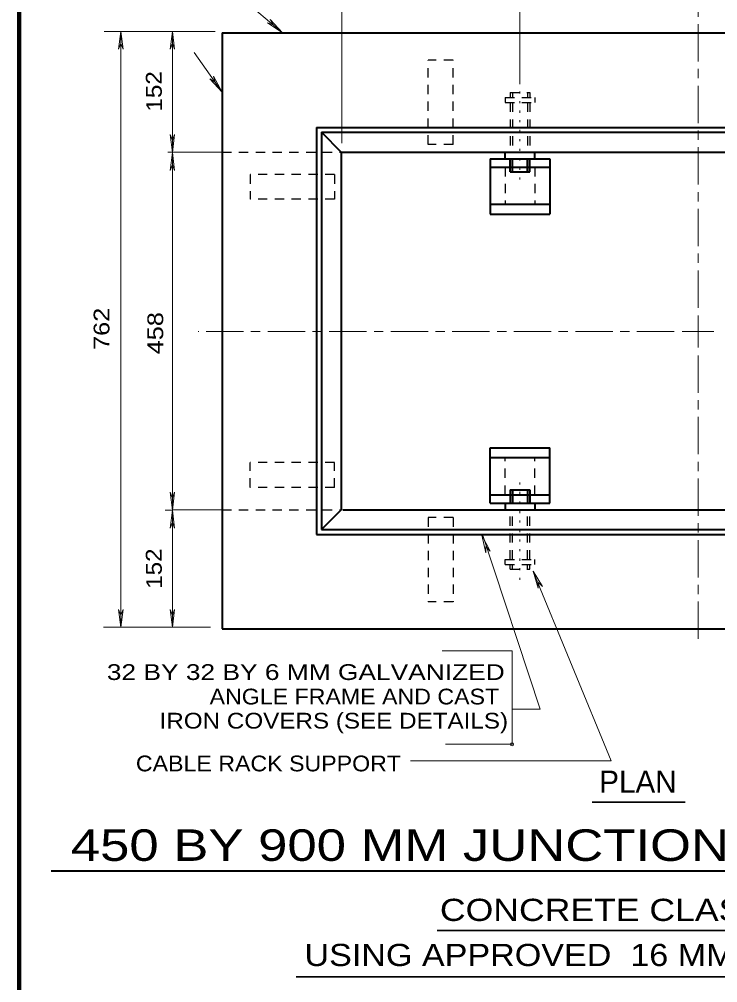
# Model space of a CAD drawing. Extents: x 312583 to 312854, y 144419 to 144597.
# Drawn here: x 312616.5 to 312650.21, y 144526.08 to 144572.55 of the extents above; entities that cross this region are included whole.
import ezdxf
from ezdxf.enums import TextEntityAlignment as Align

# ---------------------------------------------------------------- set-up
doc = ezdxf.new("R2010")
doc.units = 0
doc.header["$LTSCALE"] = 0.3
doc.header["$PDMODE"] = 32
doc.header["$PDSIZE"] = 0.15
for name, pattern in [('DOTTED', [1.5, 0.3, -1.2]), ('LONG_DASH_SHORT_DASH', [9.9, 6, -1.2, 1.5, -1.2]), ('SHORT_DASHED', [2.7, 1.5, -1.2])]:
    doc.linetypes.add(name, pattern=pattern)
doc.layers.add('1', color=7, linetype='Continuous', lineweight=40)
doc.layers.add('2', color=7, linetype='Continuous', lineweight=13)

msp = doc.modelspace()

# ---------------------------------------------------------------- linework, layer by layer
at = {"layer": '1'}
for p, q in [((312626.2931, 144571.8954), (312672.2931, 144571.8954)), ((312626.2931, 144571.8954), (312626.2931, 144543.1454)), ((312630.8471, 144567.3414), (312630.8471, 144547.6994)), ((312631.0848, 144567.1038), (312631.0848, 144547.9371)), ((312631.0848, 144567.1038), (312632.0431, 144566.1454)), ((312632.0431, 144566.1454), (312632.0431, 144548.8954)), ((312632.0508, 144566.1454), (312653.2184, 144566.1454)), ((312639.9551, 144565.8234), (312639.9551, 144566.1454)), ((312641.3888, 144565.8234), (312641.3888, 144566.1454)), ((312639.2344, 144565.8234), (312639.2344, 144563.1478)), ((312639.2344, 144565.8234), (312642.1094, 144565.8234)), ((312640.1928, 144565.1871), (312640.1928, 144565.8234)), ((312640.3078, 144565.1871), (312640.3078, 144565.8234)), ((312641.0284, 144565.1871), (312641.0284, 144565.8234)), ((312641.1511, 144565.1871), (312641.1511, 144565.8234)), ((312642.1094, 144565.8234), (312642.1094, 144563.1478)), ((312639.2344, 144565.4248), (312642.1094, 144565.4248)), ((312640.1928, 144565.1871), (312641.1511, 144565.1871)), ((312639.2344, 144563.6308), (312642.1094, 144563.6308)), ((312639.2344, 144563.1478), (312642.1094, 144563.1478)), ((312639.2344, 144551.8854), (312642.1094, 144551.8854)), ((312639.2344, 144549.2174), (312639.2344, 144551.8854)), ((312642.1094, 144549.2174), (312642.1094, 144551.8854)), ((312639.2344, 144551.4101), (312642.1094, 144551.4101)), ((312640.1928, 144549.8538), (312641.1511, 144549.8538)), ((312640.1928, 144549.8538), (312640.1928, 144549.2174)), ((312640.3078, 144549.8538), (312640.3078, 144549.2174)), ((312641.0284, 144549.8538), (312641.0284, 144549.2174)), ((312641.1511, 144549.8538), (312641.1511, 144549.2174)), ((312639.2344, 144549.6161), (312642.1094, 144549.6161)), ((312632.0431, 144548.8954), (312631.0848, 144547.9371)), ((312632.1121, 144548.8954), (312666.5354, 144548.8954)), ((312639.2344, 144549.2174), (312642.1094, 144549.2174)), ((312639.9551, 144549.2174), (312639.9551, 144548.8954)), ((312641.3888, 144549.2174), (312641.3888, 144548.8954)), ((312631.0848, 144547.9371), (312667.5014, 144547.9371)), ((312630.8471, 144547.6994), (312667.7468, 144547.6994)), ((312626.2931, 144543.1454), (312672.2931, 144543.1454))]:
    msp.add_line(p, q, dxfattribs=at)
at = {"layer": '1', "linetype": 'SHORT_DASHED', "lineweight": 25}
for p, q in [((312637.4404, 144570.5844), (312636.2368, 144570.5844)), ((312636.2368, 144566.5134), (312636.2368, 144570.5844)), ((312637.4404, 144566.5134), (312637.4404, 144570.5844)), ((312640.1928, 144569.0204), (312641.1511, 144569.0204)), ((312640.1928, 144569.0204), (312640.1928, 144568.7828)), ((312640.3078, 144569.0204), (312640.3078, 144568.7828)), ((312641.0284, 144569.0204), (312641.0284, 144568.7828)), ((312641.1511, 144569.0204), (312641.1511, 144568.7828)), ((312639.9551, 144568.7828), (312641.3888, 144568.7828)), ((312639.9551, 144568.7828), (312639.9551, 144568.5374)), ((312639.9551, 144568.5374), (312641.3888, 144568.5374)), ((312640.1928, 144568.5374), (312640.1928, 144566.1454)), ((312640.3078, 144568.5374), (312640.3078, 144566.1454)), ((312641.0284, 144568.5374), (312641.0284, 144566.1454)), ((312641.1511, 144568.5374), (312641.1511, 144566.1454)), ((312641.3888, 144568.7828), (312641.3888, 144568.5374)), ((312637.4404, 144566.5134), (312636.2368, 144566.5134)), ((312626.2931, 144566.1454), (312632.0508, 144566.1454)), ((312639.9551, 144565.4248), (312639.9551, 144563.6308)), ((312641.3888, 144565.4248), (312641.3888, 144563.6308)), ((312627.6424, 144565.0644), (312627.6424, 144563.8684)), ((312631.7134, 144565.0644), (312627.6424, 144565.0644)), ((312631.7134, 144565.0644), (312631.7134, 144563.8684)), ((312631.7134, 144563.8684), (312627.6424, 144563.8684)), ((312627.6424, 144549.9688), (312627.6424, 144551.1724)), ((312631.7134, 144551.1724), (312627.6424, 144551.1724)), ((312631.7134, 144549.9688), (312631.7134, 144551.1724)), ((312639.9551, 144549.6161), (312639.9551, 144551.4101)), ((312641.3888, 144549.6161), (312641.3888, 144551.4101)), ((312631.7134, 144549.9688), (312627.6424, 144549.9688)), ((312626.2931, 144548.8954), (312632.0431, 144548.8954)), ((312640.1928, 144546.4958), (312640.1928, 144548.8954)), ((312640.3078, 144546.4958), (312640.3078, 144548.8954)), ((312641.0284, 144546.4958), (312641.0284, 144548.8954)), ((312641.1511, 144546.4958), (312641.1511, 144548.8954)), ((312637.4404, 144548.5274), (312636.2368, 144548.5274)), ((312636.2368, 144548.5274), (312636.2368, 144544.4564)), ((312637.4404, 144548.5274), (312637.4404, 144544.4564)), ((312639.9551, 144546.4958), (312641.3888, 144546.4958)), ((312639.9551, 144546.2581), (312639.9551, 144546.4958)), ((312639.9551, 144546.2581), (312641.3888, 144546.2581)), ((312640.1928, 144546.0204), (312640.1928, 144546.2581)), ((312640.3078, 144546.0204), (312640.3078, 144546.2581)), ((312641.0284, 144546.0204), (312641.0284, 144546.2581)), ((312641.1511, 144546.0204), (312641.1511, 144546.2581)), ((312641.3888, 144546.2581), (312641.3888, 144546.4958)), ((312640.1928, 144546.0204), (312641.1511, 144546.0204)), ((312637.4404, 144544.4564), (312636.2368, 144544.4564))]:
    msp.add_line(p, q, dxfattribs=at)
at = {"layer": '1', "linetype": 'DOTTED', "lineweight": 13}
for p, q in [((312640.6681, 144569.5264), (312640.6681, 144564.7041)), ((312640.6681, 144545.5144), (312640.6681, 144550.2524))]:
    msp.add_line(p, q, dxfattribs=at)
at = {"layer": '1', "lineweight": 158}
msp.add_lwpolyline([(312616.5, 144423.1446), (312616.5, 144585.0846), (312849, 144585.0846)], dxfattribs=at)
at = {"layer": '1'}
for points in [[(312630.8471, 144567.3414), (312667.7468, 144567.3414), (312667.7468, 144547.6994)], [(312631.0848, 144567.1038), (312667.5014, 144567.1038), (312667.5014, 144547.9371)]]:
    msp.add_lwpolyline(points, dxfattribs=at)
at = {"layer": '2'}
for p, q in [((312632.0738, 144566.5824), (312632.0738, 144577.3004)), ((312640.6681, 144569.5264), (312640.6681, 144574.7551)), ((312626.8451, 144573.9118), (312629.2064, 144571.8954)), ((312628.6161, 144572.5394), (312628.7618, 144572.2788)), ((312629.2064, 144571.8954), (312628.6161, 144572.5394)), ((312628.4781, 144572.3784), (312628.7618, 144572.2788)), ((312629.2064, 144571.8954), (312628.4781, 144572.3784)), ((312620.6044, 144571.9721), (312625.9634, 144571.9721)), ((312621.4018, 144571.9721), (312621.2944, 144571.1058)), ((312621.4018, 144543.2221), (312621.4018, 144571.9721)), ((312621.4018, 144571.9721), (312621.5091, 144571.1058)), ((312623.8934, 144571.9721), (312623.7861, 144571.1058)), ((312623.8934, 144566.1301), (312623.8934, 144571.9721)), ((312623.8934, 144571.9721), (312624.0008, 144571.1058)), ((312621.2944, 144571.1058), (312621.4018, 144571.3818)), ((312621.5091, 144571.1058), (312621.4018, 144571.3818)), ((312623.7861, 144571.1058), (312623.8934, 144571.3818)), ((312624.0008, 144571.1058), (312623.8934, 144571.3818)), ((312624.9361, 144570.9524), (312626.2931, 144569.0434)), ((312625.8791, 144569.8101), (312625.9558, 144569.5188)), ((312626.2931, 144569.0434), (312625.8791, 144569.8101)), ((312625.7028, 144569.6874), (312625.9558, 144569.5188)), ((312626.2931, 144569.0434), (312625.7028, 144569.6874)), ((312623.7861, 144566.9964), (312623.8934, 144566.7204)), ((312623.8934, 144566.1301), (312623.7861, 144566.9964)), ((312624.0008, 144566.9964), (312623.8934, 144566.7204)), ((312623.8934, 144566.1301), (312624.0008, 144566.9964)), ((312626.2931, 144566.1454), (312623.6711, 144566.1454)), ((312623.8934, 144566.1301), (312623.7861, 144565.2638)), ((312623.8934, 144566.1301), (312624.0008, 144565.2638)), ((312623.7861, 144565.2638), (312623.8934, 144565.5398)), ((312624.0008, 144565.2638), (312623.8934, 144565.5398)), ((312649.2624, 144557.4898), (312649.2624, 144558.2564)), ((312649.2624, 144557.4898), (312648.4958, 144557.4898)), ((312649.2624, 144557.4898), (312649.2624, 144556.7231)), ((312649.2624, 144557.4898), (312650.0291, 144557.4898)), ((312623.7861, 144549.7388), (312623.8934, 144549.4628)), ((312623.8934, 144548.8724), (312623.7861, 144549.7388)), ((312624.0008, 144549.7388), (312623.8934, 144549.4628)), ((312623.8934, 144548.8724), (312624.0008, 144549.7388)), ((312623.9011, 144548.8724), (312623.5484, 144548.8724)), ((312623.8934, 144548.8724), (312623.7861, 144548.0061)), ((312623.8934, 144548.8724), (312624.0008, 144548.0061)), ((312626.2931, 144548.8954), (312623.9011, 144548.8954)), ((312623.7861, 144548.0061), (312623.8934, 144548.2821)), ((312624.0008, 144548.0061), (312623.8934, 144548.2821)), ((312638.8204, 144547.6688), (312639.0274, 144546.8178)), ((312638.8204, 144547.6688), (312639.2268, 144546.8944)), ((312641.6447, 144539.2775), (312638.8588, 144547.6994)), ((312639.0274, 144546.8178), (312639.0274, 144547.1168)), ((312639.2268, 144546.8944), (312639.0274, 144547.1168)), ((312641.2968, 144545.9361), (312641.5498, 144545.1081)), ((312641.2968, 144545.9361), (312641.7491, 144545.1924)), ((312645.0688, 144536.7744), (312641.3044, 144545.9208)), ((312641.5498, 144545.1081), (312641.5344, 144545.3994)), ((312641.7491, 144545.1924), (312641.5344, 144545.3994)), ((312621.2944, 144544.0884), (312621.4018, 144543.8124)), ((312621.4018, 144543.2221), (312621.2944, 144544.0884)), ((312621.5091, 144544.0884), (312621.4018, 144543.8124)), ((312621.4018, 144543.2221), (312621.5091, 144544.0884)), ((312623.7861, 144544.0884), (312623.8934, 144543.8124)), ((312623.8934, 144543.2221), (312623.7861, 144544.0884)), ((312624.0008, 144544.0884), (312623.8934, 144543.8124)), ((312623.8934, 144543.2221), (312624.0008, 144544.0884)), ((312620.5738, 144543.2221), (312625.7258, 144543.2221)), ((312640.2845, 144542.0883), (312636.9112, 144542.0883)), ((312640.2845, 144542.0883), (312640.2845, 144537.5803)), ((312640.2845, 144539.2775), (312641.6447, 144539.2775)), ((312640.2845, 144537.5803), (312637.0722, 144537.5803)), ((312635.3781, 144536.7744), (312645.0688, 144536.7744))]:
    msp.add_line(p, q, dxfattribs=at)
at = {"layer": '2', "linetype": 'LONG_DASH_SHORT_DASH'}
for p, q in [((312649.2624, 144558.6398), (312649.2624, 144577.2468)), ((312648.1124, 144557.4898), (312625.1278, 144557.4898)), ((312649.2624, 144556.3398), (312649.2624, 144542.4094))]:
    msp.add_line(p, q, dxfattribs=at)
at = {"layer": '2', "lineweight": 35}
for p, q in [((312644.1459, 144534.7926), (312648.6461, 144534.7926)), ((312636.6692, 144528.5996), (312656.7254, 144528.5996)), ((312629.8656, 144526.3655), (312662.613, 144526.3655))]:
    msp.add_line(p, q, dxfattribs=at)
at = {"layer": '2', "lineweight": 40}
msp.add_line((312618.0343, 144531.4691), (312673.2441, 144531.4691), dxfattribs=at)
at = {"layer": '2'}
msp.add_lwpolyline([(312623.8934, 144543.2221), (312623.8934, 144548.8724), (312623.8934, 144566.1301)], dxfattribs=at)
msp.add_point((312640.2845, 144537.5803), dxfattribs=at)

# ---------------------------------------------------------------- texts
at = {"layer": '1'}
for s, rotation, width, p in [('152 ', 90.814, 1.15, (312623.3924, 144568.1068)), ('458 ', 90, 1.2, (312623.4461, 144556.3916)), ('152 ', 90.814, 1.15, (312623.3924, 144545.0838))]:
    msp.add_text(s, height=0.76, rotation=rotation, dxfattribs=dict(at, width=width)).set_placement(p)
for s, width, p in [('32 BY 32 BY 6 MM GALVANIZED', 1.25, (312620.7272, 144540.6814)), ('ANGLE FRAME AND CAST', 1.1, (312625.687, 144539.5017)), ('IRON COVERS (SEE DETAILS)', 1.15, (312623.273, 144538.3374)), ('CABLE RACK SUPPORT', 1.1, (312622.1293, 144536.2741))]:
    msp.add_text(s, height=0.76, dxfattribs=dict(at, width=width)).set_placement(p)
at = {"layer": '2', "width": 1.2}
msp.add_text('762 ', height=0.76, rotation=90, dxfattribs=at).set_placement((312620.8514, 144556.6036))
at = {"layer": '2'}
msp.add_text('PLAN', height=1.07, dxfattribs=at).set_placement((312646.3622, 144535.2391), align=Align.CENTER)
for s, height, width, p in [('450 BY 900 MM JUNCTION BOX - CLASS "JB"', 1.52, 1.25, (312645.9415, 144531.954)), ('CONCRETE CLASS " C "', 1.07, 1.2, (312646.6205, 144529.0568)), ('USING APPROVED  16 MM  AGGREGATE', 1.07, 1.15, (312646.3134, 144526.8814))]:
    msp.add_text(s, height=height, dxfattribs=dict(at, width=width)).set_placement(p, align=Align.CENTER)

doc.saveas('drawing.dxf')
